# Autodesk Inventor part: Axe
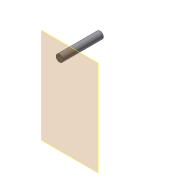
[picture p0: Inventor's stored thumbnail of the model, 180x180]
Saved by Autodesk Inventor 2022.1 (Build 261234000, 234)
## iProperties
Created: 2021-07
Part Number: Axe
Material: Générique
Document SubType Name: Modeling
Designer: Fabian
Density: 1 g/cm^3
Appearance: Par défaut
Author: Fabian
DocNumber: Axe.ipt
Folder: .\
VDS_Category: Ingénierie
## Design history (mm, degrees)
node "Plan de construction1"
sketch "Esquisse1"
  geometry: C1 r 2.5 at (-11.513, 19.133) reference; C2 r 2.4 at (-11.513, 19.133); 1 further point
  constraints: 1 centre point
  dimensions: "d0" = 0.1 radial gap between concentric circles of C1 C2
  node "Référence1"
node "Plan de construction2"
extrude "Extrusion1" new body sketch "Esquisse1" stored distance "d1" = 10; taper "d2" = 0 deg
feature "Filetage1" dims "d3" = 3, "d4" = 0
chamfer "Chanfrein1" distance "d5" = 0.5; stored, may be unused: second distance "d6" = 2, angle "d7" = 45 deg
sketch "Esquisse2"
  geometry: L1 (-1, 0.577)-(0, 1.155); L2 (0, 1.155)-(1, 0.577); L3 (1, 0.577)-(1, -0.577); L4 (1, -0.577)-(0, -1.155); L5 (0, -1.155)-(-1, -0.577); L6 (-1, -0.577)-(-1, 0.577); C1 r 1.9 at (0, 0) reference; 2 further points
  constraints: 12 end point, 1 coincident, 1 vertical, 13 other
  dimensions: "d8" = 2 distance between parallel lines of L2 L5
extrude "Extrusion2" cut sketch "Esquisse2" distance "d9" = 2; taper "d10" = 0 deg
node "Solide1"
node "Boucle projetée1"
